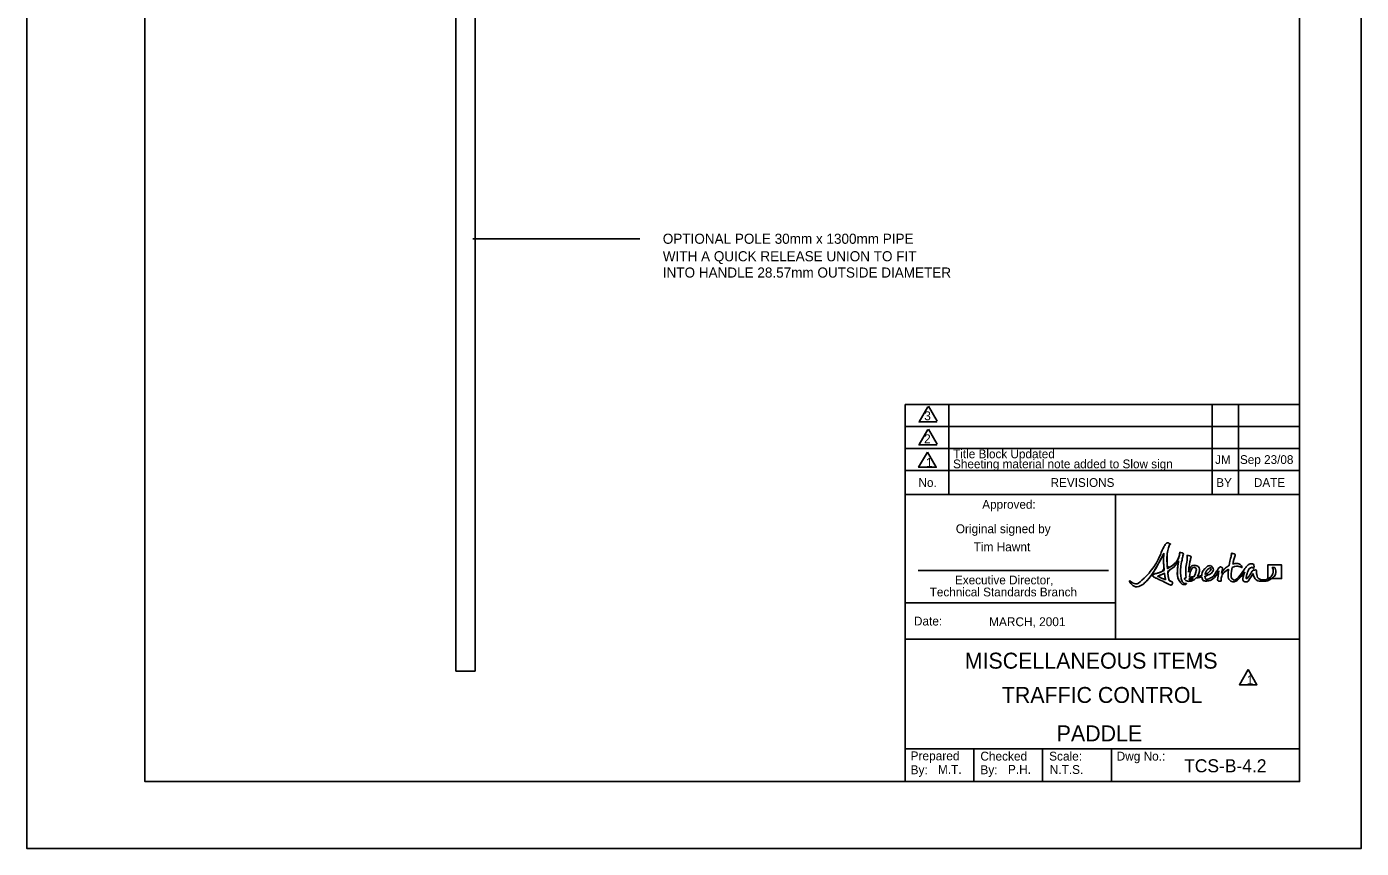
# Model space of a CAD drawing. Extents: x -16491 to -16265, y 453039 to 453318.
# Drawn here: x -16490.6 to -16274.6, y 453038.9 to 453171.9 of the extents above; entities that cross this region are included whole.
import ezdxf

# ---------------------------------------------------------------- set-up
doc = ezdxf.new("R2010")
doc.units = 0
for name, color, linetype in [('Level 1', 7, 'Continuous'), ('Level 10', 7, 'Continuous'), ('Level 2', 7, 'Continuous'), ('Level 22', 7, 'Continuous'), ('Level 44', 7, 'Continuous'), ('Level 45', 7, 'Continuous'), ('Level 53', 7, 'Continuous'), ('Level 60', 7, 'Continuous'), ('Level 63', 7, 'Continuous'), ('Level 7', 7, 'Continuous')]:
    doc.layers.add(name, color=color, linetype=linetype)

msp = doc.modelspace()

# ---------------------------------------------------------------- linework, layer by layer
at = {"layer": 'Level 1'}
for p, q in [((-16418.4, 453137.55), (-16391.33, 453137.55)), ((-16348.42, 453049.67), (-16348.42, 453096.14)), ((-16314.37, 453096.14), (-16314.37, 453072.73)), ((-16348.42, 453078.58), (-16314.37, 453078.58)), ((-16348.42, 453072.73), (-16284.58, 453072.73)), ((-16348.42, 453054.99), (-16284.58, 453054.99)), ((-16337.29, 453049.67), (-16337.29, 453054.99)), ((-16326.16, 453049.67), (-16326.16, 453054.99)), ((-16315.03, 453054.99), (-16315.03, 453049.67))]:
    msp.add_line(p, q, dxfattribs=at)
for points in [[(-16421.11, 453182.03), (-16418.01, 453182.03), (-16418.01, 453067.55), (-16421.11, 453067.55)], [(-16292.89, 453067.81), (-16294.31, 453065.34), (-16291.47, 453065.34)]]:
    msp.add_lwpolyline(points, close=True, dxfattribs=at)
at = {"layer": 'Level 10'}
msp.add_line((-16284.58, 453049.67), (-16284.58, 453049.67), dxfattribs=at)
msp.add_line((-16284.58, 453049.67), (-16284.58, 453049.67), dxfattribs=at)
at = {"layer": 'Level 2'}
msp.add_line((-16314.37, 453096.14), (-16314.37, 453096.14), dxfattribs=at)
at = {"layer": 'Level 22'}
msp.add_line((-16332.96, 453049.67), (-16332.96, 453049.67), dxfattribs=at)
at = {"layer": 'Level 44'}
for p, q in [((-16284.55, 453110.69), (-16348.43, 453110.69)), ((-16284.55, 453107.14), (-16348.43, 453107.14)), ((-16284.55, 453103.59), (-16348.43, 453103.59)), ((-16284.55, 453100.04), (-16348.43, 453100.04)), ((-16348.42, 453096.14), (-16284.55, 453096.14))]:
    msp.add_line(p, q, dxfattribs=at)
msp.add_lwpolyline([(-16344.8, 453103.02), (-16346.22, 453100.55), (-16343.38, 453100.55)], close=True, dxfattribs=at)
at = {"layer": 'Level 45'}
msp.add_line((-16314.36, 453096.14), (-16314.36, 453096.14), dxfattribs=at)
at = {"layer": 'Level 53'}
msp.add_line((-16289.09, 453082.52), (-16289.65, 453082.52), dxfattribs=at)
msp.add_lwpolyline([(-16289.09, 453082.52), (-16287.48, 453082.52), (-16287.48, 453084.75), (-16289.71, 453084.75), (-16289.71, 453082.52), (-16289.65, 453082.52)], dxfattribs=at)
for points, degree in [([(-16303.08, 453081.71), (-16303.32, 453081.74), (-16303.63, 453082.07), (-16303.73, 453082.61), (-16303.9, 453083.57), (-16303.8, 453084.53), (-16303.51, 453085.95), (-16303.46, 453086.22), (-16303.28, 453086.68), (-16303.86, 453086.77), (-16304.05, 453086.8), (-16303.95, 453086.71), (-16304, 453086.46), (-16304.23, 453085.41), (-16305.09, 453084.64), (-16305.96, 453084.13), (-16306.05, 453085.34), (-16306.02, 453086.69), (-16305.79, 453087.51), (-16305.59, 453088.21), (-16305.37, 453088.08), (-16305.65, 453088.23), (-16305.95, 453088.38), (-16306.27, 453088.18), (-16306.53, 453087.66), (-16306.79, 453087.14), (-16307.99, 453084.33), (-16309.9, 453082.43), (-16310.88, 453081.45), (-16311.76, 453081.95), (-16311.94, 453082.1), (-16312.08, 453082.23), (-16312.13, 453082.04), (-16311.96, 453081.85), (-16311.16, 453080.99), (-16310.01, 453081.48), (-16309.59, 453081.9), (-16308.43, 453083.06), (-16307.07, 453085.57), (-16306.53, 453086.63), (-16306.58, 453086.03), (-16306.59, 453085.03), (-16306.48, 453083.85), (-16307.07, 453083.56), (-16307.6, 453083.4), (-16307.86, 453083.33), (-16308.13, 453083.26), (-16308.29, 453083.15), (-16308.3, 453083.02), (-16308.3, 453082.88), (-16308.12, 453082.77), (-16307.86, 453082.64), (-16307.39, 453082.42), (-16306.02, 453081.77), (-16305.68, 453081.58), (-16305.39, 453081.41), (-16305.25, 453081.54), (-16305.16, 453081.72), (-16305.05, 453081.96), (-16305.36, 453082.09), (-16305.66, 453082.18), (-16305.77, 453082.58), (-16305.86, 453083.12), (-16305.92, 453083.71), (-16305.23, 453084.14), (-16304.54, 453084.71), (-16304.14, 453085.42), (-16304.24, 453084.82), (-16304.5, 453082.79), (-16303.86, 453081.94), (-16303.72, 453081.75), (-16303.41, 453081.54), (-16303.1, 453081.57), (-16302.96, 453081.58), (-16302.88, 453081.68), (-16302.9, 453081.71), (-16302.91, 453081.74), (-16303, 453081.7), (-16303.08, 453081.71)], 3), ([(-16305.96, 453084.13), (-16306.05, 453085.34), (-16306.02, 453086.69), (-16305.79, 453087.51), (-16305.59, 453088.21), (-16305.37, 453088.08), (-16305.65, 453088.23), (-16305.95, 453088.38), (-16306.27, 453088.18), (-16306.53, 453087.66), (-16306.79, 453087.14), (-16307.99, 453084.33), (-16309.9, 453082.43), (-16310.88, 453081.45), (-16311.76, 453081.95), (-16311.94, 453082.1), (-16312.08, 453082.23), (-16312.13, 453082.04), (-16311.96, 453081.85), (-16311.16, 453080.99), (-16310.01, 453081.48), (-16309.59, 453081.9), (-16308.43, 453083.06), (-16307.07, 453085.57), (-16306.53, 453086.63)], 3), ([(-16306.53, 453086.63), (-16306.58, 453086.03), (-16306.59, 453085.03), (-16306.48, 453083.85)], 2), ([(-16303.08, 453081.71), (-16303.32, 453081.74), (-16303.63, 453082.07), (-16303.73, 453082.61), (-16303.9, 453083.57), (-16303.8, 453084.53), (-16303.51, 453085.95), (-16303.46, 453086.22), (-16303.28, 453086.68), (-16303.86, 453086.77), (-16304.05, 453086.8), (-16303.95, 453086.71), (-16304, 453086.46), (-16304.23, 453085.41), (-16305.09, 453084.64), (-16305.96, 453084.13)], 3), ([(-16302.54, 453083.55), (-16302.5, 453084.12), (-16302.41, 453084.81), (-16302.28, 453085.45), (-16302.22, 453085.72), (-16302.04, 453086.19), (-16302.62, 453086.28), (-16302.81, 453086.31), (-16302.78, 453086.22), (-16302.77, 453085.97), (-16302.74, 453085.63), (-16303.12, 453083.59), (-16302.92, 453082.7)], 3), ([(-16295.39, 453084.89), (-16295.32, 453085.19), (-16295.25, 453085.49), (-16295.17, 453085.78), (-16295.09, 453086.05), (-16294.87, 453086.52), (-16295.45, 453086.61), (-16295.63, 453086.64), (-16295.55, 453086.55), (-16295.61, 453086.3), (-16295.72, 453085.84), (-16295.86, 453085.25), (-16295.97, 453084.65)], 3), ([(-16306.48, 453083.85), (-16307.07, 453083.56), (-16307.6, 453083.4), (-16307.86, 453083.33), (-16308.13, 453083.26), (-16308.29, 453083.15), (-16308.3, 453083.02), (-16308.3, 453082.88), (-16308.12, 453082.77), (-16307.86, 453082.64), (-16307.39, 453082.42), (-16306.02, 453081.77), (-16305.68, 453081.58), (-16305.39, 453081.41), (-16305.25, 453081.54), (-16305.16, 453081.72), (-16305.05, 453081.96), (-16305.36, 453082.09), (-16305.66, 453082.18)], 3), ([(-16305.92, 453083.71), (-16305.23, 453084.14), (-16304.54, 453084.71), (-16304.14, 453085.42)], 2), ([(-16304.14, 453085.42), (-16304.24, 453084.82), (-16304.5, 453082.79), (-16303.86, 453081.94), (-16303.72, 453081.75), (-16303.41, 453081.54), (-16303.1, 453081.57), (-16302.96, 453081.58), (-16302.88, 453081.68), (-16302.9, 453081.71), (-16302.91, 453081.74), (-16303, 453081.7), (-16303.08, 453081.71)], 3), ([(-16301.11, 453082.89), (-16300.69, 453083.56), (-16300.73, 453084.47), (-16301.33, 453084.62), (-16302.04, 453084.8), (-16302.39, 453084.12), (-16302.54, 453083.55)], 3), ([(-16302.39, 453082.76), (-16302.3, 453083.48), (-16301.93, 453084.47), (-16301.46, 453084.31), (-16301.19, 453084.22), (-16301.34, 453083.38), (-16301.68, 453082.82)], 3), ([(-16299.88, 453082.91), (-16299.78, 453082.94), (-16299.7, 453082.97), (-16299.62, 453083), (-16298.74, 453083.4), (-16298.44, 453083.99), (-16298.66, 453084.34), (-16298.88, 453084.69), (-16299.48, 453084.58), (-16299.96, 453084.08), (-16300.2, 453083.83), (-16300.38, 453083.4), (-16300.41, 453083.01)], 3), ([(-16300.4, 453082.79), (-16300.35, 453082.39), (-16300.09, 453082.09), (-16299.5, 453082.15), (-16298.65, 453082.23), (-16297.9, 453083.27), (-16297.62, 453083.77)], 3), ([(-16297.2, 453083.33), (-16297.15, 453083.6), (-16297.06, 453083.91), (-16297.06, 453084.11), (-16297.05, 453084.33), (-16297.2, 453084.38), (-16297.26, 453084.4), (-16297.38, 453084.43), (-16297.54, 453084.37), (-16297.69, 453084.16), (-16298.04, 453083.66), (-16298.49, 453082.87), (-16299.17, 453082.54), (-16299.65, 453082.31), (-16299.87, 453082.54), (-16299.88, 453082.91)], 3), ([(-16299.41, 453084.03), (-16299.11, 453084.31), (-16298.96, 453084.29), (-16298.93, 453084.21), (-16298.84, 453084.05), (-16299.19, 453083.49), (-16299.86, 453083.18)], 3), ([(-16299.86, 453083.18), (-16299.8, 453083.48), (-16299.64, 453083.81), (-16299.41, 453084.03)], 2), ([(-16297.62, 453083.77), (-16297.67, 453083.23), (-16298.02, 453082.06), (-16297.42, 453082.12), (-16297.19, 453082.14), (-16297.29, 453082.18), (-16297.28, 453082.38), (-16297.22, 453083.09), (-16296.64, 453083.69), (-16296.05, 453084.05)], 3), ([(-16295.97, 453084.65), (-16296.44, 453084.38), (-16296.88, 453083.93), (-16297.2, 453083.33)], 2), ([(-16296.05, 453084.05), (-16296.15, 453083.19), (-16296.12, 453082.41), (-16295.73, 453082.17), (-16295.01, 453081.72), (-16293.98, 453082.91), (-16293.42, 453083.63)], 3), ([(-16290.33, 453082.32), (-16291.25, 453082.32), (-16291.49, 453083.03), (-16291.53, 453083.38), (-16291.56, 453083.62), (-16291.51, 453083.96), (-16291.91, 453083.91), (-16292.2, 453083.88), (-16292.45, 453083.33), (-16292.81, 453082.86), (-16293.12, 453082.47), (-16293.26, 453082.5), (-16293.19, 453082.85), (-16293.1, 453083.27), (-16292.74, 453084.28), (-16292.33, 453084.35), (-16292.14, 453084.39), (-16292.07, 453084.05), (-16291.99, 453084.26), (-16291.9, 453084.47), (-16291.98, 453084.92), (-16292.4, 453084.92), (-16292.7, 453084.92), (-16293.05, 453084.61), (-16293.35, 453084.25), (-16293.6, 453083.94), (-16294.89, 453082.04), (-16295.42, 453082.45), (-16295.68, 453082.64), (-16295.66, 453083.42), (-16295.5, 453084.34)], 3), ([(-16295.5, 453084.34), (-16294.86, 453084.58), (-16294.33, 453084.5), (-16294.02, 453084.36), (-16293.88, 453084.29), (-16293.86, 453084.3), (-16293.92, 453084.46), (-16294.01, 453084.7), (-16294.53, 453085.08), (-16295.33, 453084.9), (-16295.35, 453084.9), (-16295.37, 453084.9), (-16295.39, 453084.89)], 3), ([(-16289.71, 453084.75), (-16289.71, 453084.75), (-16289.71, 453082.52), (-16289.71, 453082.52), (-16289.71, 453082.52), (-16289.65, 453082.52), (-16289.65, 453082.52), (-16289.16, 453082.81), (-16288.84, 453083.36), (-16288.84, 453083.82), (-16288.84, 453084.21), (-16289.04, 453084.19), (-16289.02, 453084.25), (-16288.95, 453084.4), (-16288.46, 453084.31), (-16288.43, 453083.76), (-16288.41, 453083.29), (-16288.65, 453082.83), (-16289.09, 453082.52), (-16289.09, 453082.52), (-16287.48, 453082.52), (-16287.48, 453082.52), (-16287.48, 453082.52), (-16287.48, 453084.75), (-16287.48, 453084.75), (-16287.48, 453084.75), (-16289.71, 453084.75), (-16289.71, 453084.75)], 3), ([(-16289.65, 453082.52), (-16289.16, 453082.81), (-16288.84, 453083.36), (-16288.84, 453083.82), (-16288.84, 453084.21), (-16289.04, 453084.19), (-16289.02, 453084.25), (-16288.95, 453084.4), (-16288.46, 453084.31), (-16288.43, 453083.76), (-16288.41, 453083.29), (-16288.65, 453082.83), (-16289.09, 453082.52)], 3), ([(-16307.55, 453082.92), (-16307.24, 453083.03), (-16306.85, 453083.2), (-16306.44, 453083.42)], 2), ([(-16307.55, 453082.92), (-16307.24, 453083.03), (-16306.85, 453083.2), (-16306.44, 453083.42), (-16306.38, 453082.94), (-16306.32, 453082.6), (-16306.25, 453082.35), (-16306.55, 453082.46), (-16306.99, 453082.63), (-16307.55, 453082.92)], 3), ([(-16306.25, 453082.35), (-16306.55, 453082.46), (-16306.99, 453082.63), (-16307.55, 453082.92)], 2), ([(-16306.44, 453083.42), (-16306.38, 453082.94), (-16306.32, 453082.6), (-16306.25, 453082.35)], 2), ([(-16305.66, 453082.18), (-16305.77, 453082.58), (-16305.86, 453083.12), (-16305.92, 453083.71)], 2), ([(-16302.92, 453082.7), (-16303.17, 453082.62), (-16303.28, 453082.43), (-16302.95, 453082.23), (-16302.73, 453082.09), (-16302.24, 453082.05), (-16301.75, 453082.29), (-16301.57, 453082.38), (-16301.41, 453082.5), (-16301.29, 453082.64)], 3), ([(-16302.47, 453082.33), (-16302.44, 453082.35), (-16302.42, 453082.39), (-16302.42, 453082.44), (-16302.42, 453082.47), (-16302.42, 453082.51), (-16302.41, 453082.54)], 3), ([(-16302.27, 453082.33), (-16302.35, 453082.32), (-16302.41, 453082.32), (-16302.47, 453082.33)], 2), ([(-16302.41, 453082.54), (-16302.29, 453082.54), (-16302.09, 453082.56), (-16301.86, 453082.58)], 2), ([(-16301.68, 453082.82), (-16301.9, 453082.8), (-16302.14, 453082.78), (-16302.39, 453082.76)], 2), ([(-16301.86, 453082.58), (-16301.98, 453082.45), (-16302.12, 453082.35), (-16302.27, 453082.33)], 2), ([(-16301.29, 453082.64), (-16300.99, 453082.68), (-16300.68, 453082.73), (-16300.4, 453082.79)], 2), ([(-16300.41, 453083.01), (-16300.61, 453082.96), (-16300.84, 453082.92), (-16301.11, 453082.89)], 2), ([(-16293.42, 453083.63), (-16293.71, 453082.99), (-16293.87, 453082.16), (-16293.44, 453082.03), (-16292.93, 453081.89), (-16292.54, 453082.72), (-16292.07, 453083.37)], 3), ([(-16292.07, 453083.37), (-16292.02, 453082.91), (-16291.71, 453082.11), (-16290.47, 453082.11), (-16289.92, 453082.11), (-16289.44, 453082.27), (-16289.09, 453082.52)], 3), ([(-16289.65, 453082.52), (-16289.85, 453082.4), (-16290.08, 453082.32), (-16290.33, 453082.32)], 2)]:
    msp.add_open_spline(points, degree=degree, dxfattribs=at)
at = {"layer": 'Level 60'}
for p, q in [((-16284.58, 453049.67), (-16284.58, 453049.67)), ((-16481.45, 453038.86), (-16481.45, 453038.86)), ((-16274.58, 453038.86), (-16274.58, 453038.86))]:
    msp.add_line(p, q, dxfattribs=at)
for points in [[(-16490.58, 453317.86), (-16274.58, 453317.86), (-16274.58, 453038.86), (-16490.58, 453038.86)], [(-16471.45, 453307.06), (-16284.58, 453307.06), (-16284.58, 453049.67), (-16471.45, 453049.67)]]:
    msp.add_lwpolyline(points, close=True, dxfattribs=at)
at = {"layer": 'Level 63'}
for p, q in [((-16348.42, 453104.22), (-16348.42, 453110.69)), ((-16341.33, 453104.22), (-16341.33, 453110.69)), ((-16298.74, 453110.69), (-16298.74, 453096.14)), ((-16294.43, 453110.69), (-16294.43, 453096.14)), ((-16348.42, 453096.14), (-16348.42, 453104.22)), ((-16341.33, 453096.14), (-16341.33, 453104.22))]:
    msp.add_line(p, q, dxfattribs=at)
for points in [[(-16344.72, 453110.36), (-16346.12, 453107.93)], [(-16343.24, 453108.01), (-16344.64, 453110.43)], [(-16346.12, 453107.93), (-16346.14, 453107.89), (-16343.3, 453107.89), (-16343.33, 453107.93)], [(-16344.72, 453106.64), (-16346.12, 453104.22)], [(-16343.24, 453104.29), (-16344.64, 453106.72)], [(-16346.12, 453104.22), (-16346.14, 453104.17), (-16343.3, 453104.17), (-16343.33, 453104.22)]]:
    msp.add_lwpolyline(points, dxfattribs=at)
at = {"layer": 'Level 7'}
msp.add_line((-16346.32, 453083.82), (-16315.52, 453083.82), dxfattribs=at)

# ---------------------------------------------------------------- texts
at = {"layer": 'Level 1'}
for s, height, p in [('OPTIONAL POLE 30mm x 1300mm PIPE', 1.6352, (-16387.63, 453136.73)), ('WITH A QUICK RELEASE UNION TO FIT', 1.6352, (-16387.63, 453133.9)), ('INTO HANDLE 28.57mm OUTSIDE DIAMETER', 1.6352, (-16387.63, 453131.26)), ('MISCELLANEOUS ITEMS ', 2.585, (-16338.76, 453067.95)), ('TRAFFIC CONTROL ', 2.5849, (-16332.76, 453062.4)), ('PADDLE', 2.585, (-16323.88, 453056.18))]:
    msp.add_text(s, height=height, dxfattribs=at).set_placement(p)
for s, height, p in [('Date:', 1.433, (-16346.99, 453074.94)), ('1', 1.45, (-16293.12, 453065.4)), ('Prepared', 1.44, (-16347.53, 453053.11)), ('Checked', 1.433, (-16336.23, 453053.07)), ('Scale:', 1.433, (-16325.1, 453053.07)), ('Dwg No.:', 1.433, (-16314.18, 453053.07)), ('By:', 1.44, (-16347.53, 453050.86)), ('By:', 1.44, (-16336.23, 453050.86)), ('    N.T.S.   ', 1.433, (-16327.13, 453050.9))]:
    msp.add_text(s, height=height, rotation=360, dxfattribs=at).set_placement(p)
at = {"layer": 'Level 44'}
for s, height, p in [('3', 1.45, (-16345.33, 453108.16)), ('2', 1.45, (-16345.35, 453104.44)), ('1', 1.45, (-16345.03, 453100.61)), ('JM', 1.419, (-16298.24, 453101.09)), ('Sep 23/08', 1.419, (-16294.22, 453101.09)), ('No.', 1.419, (-16346.25, 453097.37)), ('REVISIONS', 1.419, (-16324.87, 453097.37)), ('BY', 1.419, (-16298.06, 453097.37)), ('DATE', 1.419, (-16291.96, 453097.37))]:
    msp.add_text(s, height=height, rotation=360, dxfattribs=at).set_placement(p)
at = {"layer": 'Level 60'}
for s, height, p in [('MARCH, 2001', 1.434, (-16334.82, 453074.83)), ('TCS-B-4.2', 2.11, (-16303.25, 453051.17))]:
    msp.add_text(s, height=height, dxfattribs=at).set_placement(p)
for s, p in [('M.T.', (-16343.1, 453050.92)), ('P.H.', (-16331.77, 453050.92))]:
    msp.add_text(s, height=1.433, rotation=360, dxfattribs=at).set_placement(p)
at = {"layer": 'Level 7'}
for s, height, p in [('Title Block Updated', 1.419, (-16340.64, 453102.01)), ('Sheeting material note added to Slow sign', 1.419, (-16340.65, 453100.39)), ('Approved:', 1.419, (-16335.93, 453093.84)), ('Original signed by', 1.434, (-16340.21, 453089.88)), ('Tim Hawnt', 1.434, (-16337.32, 453086.95)), ('Executive Director,', 1.4187, (-16340.34, 453081.6)), ('Technical Standards Branch', 1.4187, (-16344.43, 453079.65))]:
    msp.add_text(s, height=height, dxfattribs=at).set_placement(p)

doc.saveas('drawing.dxf')
